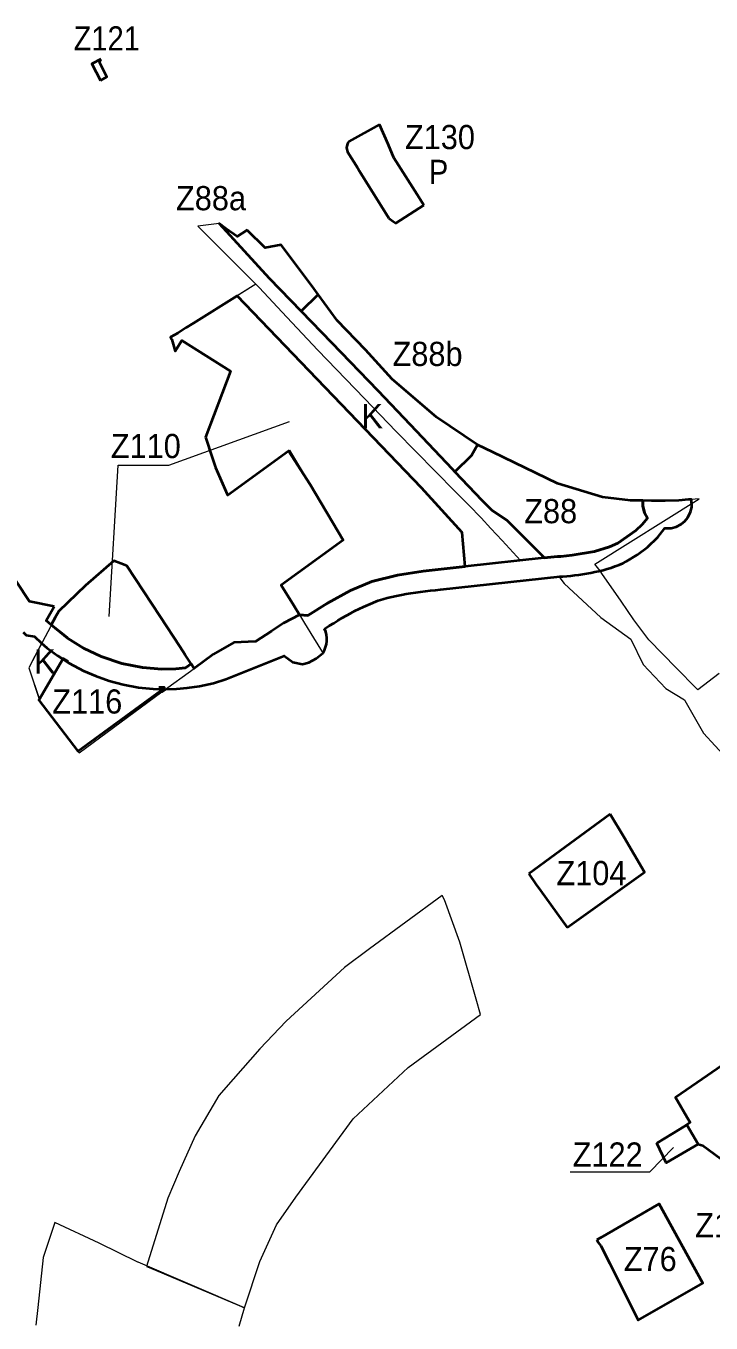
# Model space of a CAD drawing. Extents: x -650276 to -642489, y -1074311 to -1066658.
# Drawn here: x -647405 to -646724, y -1072934 to -1071646 of the extents above; entities that cross this region are included whole.
import ezdxf

# ---------------------------------------------------------------- set-up
doc = ezdxf.new("R2010")
doc.units = 0
doc.header["$LTSCALE"] = 9.6
for name, color, linetype, lineweight in [('44', 7, 'Continuous', 40), ('45', 7, 'Continuous', 40), ('46', 7, 'Continuous', 13), ('47', 7, 'Continuous', 13), ('48', 7, 'Continuous', 13), ('60', 7, 'Continuous', 35), ('63', 7, 'Continuous', 13)]:
    doc.layers.add(name, color=color, linetype=linetype, lineweight=lineweight)

msp = doc.modelspace()

# ---------------------------------------------------------------- linework, layer by layer
at = {"layer": '44'}
msp.add_line((-646978.602, -1072088.66), (-646951.95, -1072116.84), dxfattribs=at)
for points in [[(-646790.432, -1072129.195), (-646791.977, -1072122.305), (-646791.84, -1072117.172), (-646804.27, -1072116.98), (-646832.01, -1072113.66), (-646876.83, -1072100.12), (-646941.054, -1072069.172), (-646956.04, -1072061.95), (-646962.041, -1072072.379), (-646978.602, -1072088.66)], [(-646951.95, -1072116.84), (-646941.45, -1072126.84), (-646927.14, -1072136.74), (-646891.05, -1072172.79), (-646890.044, -1072174.056), (-646876.712, -1072172.592), (-646873.495, -1072172.799), (-646862.09, -1072171.444), (-646840.102, -1072167.623), (-646825.169, -1072163.164), (-646816.74, -1072159.571), (-646799, -1072147), (-646792.58, -1072140.847), (-646787.481, -1072134.643), (-646790.432, -1072129.195)], [(-646808.466, -1072177.78), (-646797.713, -1072171.151), (-646787.223, -1072163.402), (-646777.129, -1072153.576), (-646770.057, -1072144.677), (-646763.959, -1072144.535), (-646758.736, -1072143.137), (-646753.929, -1072140.612), (-646750.164, -1072137.467), (-646747.39, -1072134.069), (-646744.554, -1072128.415), (-646743.411, -1072123.612), (-646743.596, -1072115.985), (-646746.547, -1072116.221), (-646756.298, -1072117), (-646769.668, -1072117.517), (-646783.449, -1072117.302), (-646791.84, -1072117.172)], [(-646791.84, -1072117.172), (-646791.977, -1072122.305), (-646790.432, -1072129.195)], [(-647376.68, -1072222.29), (-647401.221, -1072217.342), (-647451.21, -1072142.08), (-647452.23, -1072134.91)], [(-646790.432, -1072129.195), (-646787.481, -1072134.643), (-646792.58, -1072140.847), (-646799, -1072147), (-646816.74, -1072159.571), (-646825.169, -1072163.164), (-646840.102, -1072167.623), (-646862.09, -1072171.444), (-646873.495, -1072172.799), (-646876.712, -1072172.592), (-646890.044, -1072174.056), (-646968.503, -1072182.672)], [(-646968.503, -1072182.672), (-646995.137, -1072185.597), (-647010.148, -1072187.308), (-647035.515, -1072191.104), (-647060.973, -1072197.439), (-647082.249, -1072206.591), (-647104.989, -1072219.005), (-647124.81, -1072231.168), (-647133, -1072230.754), (-647148.71, -1072238.76)], [(-646851.567, -1072190.155), (-646847.575, -1072189.507), (-646843.569, -1072188.789), (-646843.535, -1072188.782), (-646839.556, -1072187.988), (-646835.538, -1072187.097)], [(-646835.538, -1072187.097), (-646831.517, -1072186.103), (-646827.501, -1072184.997), (-646823.496, -1072183.769), (-646819.509, -1072182.408), (-646815.549, -1072180.906), (-646811.621, -1072179.254), (-646808.466, -1072177.78)], [(-647017.46, -1072208.427), (-647012.612, -1072207.773), (-647007.734, -1072207.162), (-647002.826, -1072206.583), (-646997.894, -1072206.024), (-646992.937, -1072205.475), (-646874.517, -1072192.471), (-646871.271, -1072192.675)], [(-646871.271, -1072192.675), (-646867.371, -1072192.234), (-646867.32, -1072192.228), (-646863.448, -1072191.771), (-646859.506, -1072191.276), (-646855.545, -1072190.741), (-646851.567, -1072190.155)], [(-647108.131, -1072244.373), (-647103.164, -1072241.306), (-647098.944, -1072238.718), (-647094.737, -1072236.177), (-647090.531, -1072233.695), (-647086.322, -1072231.285), (-647082.102, -1072228.962), (-647077.867, -1072226.739), (-647073.611, -1072224.631), (-647069.33, -1072222.651), (-647064.868, -1072220.746), (-647054.841, -1072216.479), (-647050.344, -1072215.107), (-647045.786, -1072213.858), (-647041.174, -1072212.723), (-647036.512, -1072211.693), (-647031.807, -1072210.758), (-647027.061, -1072209.91), (-647022.278, -1072209.136), (-647017.46, -1072208.427)], [(-647240.55, -1072279.42), (-647246.206, -1072283.328), (-647255.671, -1072284.192), (-647269.579, -1072284.489), (-647288.769, -1072283.003), (-647309.416, -1072278.875), (-647330.032, -1072271.935), (-647347.382, -1072263.623), (-647363.317, -1072253.632), (-647363.786, -1072253.254), (-647379.422, -1072240.675), (-647384.567, -1072236.256), (-647376.68, -1072222.29)], [(-647148.71, -1072238.76), (-647160.91, -1072246.82), (-647176.7, -1072257.24), (-647198.3, -1072258.09), (-647218.35, -1072269.67), (-647237.6, -1072283.78), (-647240.55, -1072279.42)], [(-647407.34, -1072247.93), (-647404.45, -1072250.66), (-647396.25, -1072252.14), (-647389.072, -1072258.845)], [(-647389.072, -1072258.845), (-647383.813, -1072263.219), (-647372.858, -1072271.363), (-647361.521, -1072278.584), (-647347.369, -1072286.111)], [(-647205.975, -1072294.599), (-647148.171, -1072271.47), (-647139.697, -1072277.484), (-647130.12, -1072279.44), (-647123.774, -1072277.899)], [(-647123.774, -1072277.899), (-647116.323, -1072273.885), (-647109.812, -1072268.588)], [(-647347.369, -1072286.111), (-647335.382, -1072291.341), (-647321.953, -1072296.073), (-647308.157, -1072299.786), (-647292.715, -1072302.646), (-647278.108, -1072304.147), (-647271.395, -1072304.452), (-647269.52, -1072307.17), (-647265.793, -1072304.439)], [(-647265.793, -1072304.439), (-647255.16, -1072304.123), (-647244.428, -1072303.192), (-647232.368, -1072301.4), (-647218.5, -1072298.335), (-647205.975, -1072294.599)]]:
    msp.add_lwpolyline(points, dxfattribs=at)
msp.add_arc((-647130.12, -1072255.012), 24.428, 326.23773, 25.81772, dxfattribs=at)
at = {"layer": '45'}
for points in [[(-647330.34, -1071678.82), (-647339.211, -1071683.431), (-647330.73, -1071700.09)], [(-647330.73, -1071700.09), (-647324.21, -1071696.2), (-647331.65, -1071681.7), (-647330.34, -1071678.82)], [(-647053.43, -1071743.63), (-647083.97, -1071760.74), (-647084.95, -1071761.98), (-647085.71, -1071763.75), (-647086.19, -1071766.95), (-647085.25, -1071770.69), (-647074.99, -1071786.99), (-647073.19, -1071789.9), (-647044.12, -1071836.68)], [(-647009.514, -1071823.81), (-647016.12, -1071813.35), (-647039.14, -1071776.9), (-647044.83, -1071763.37), (-647053.43, -1071743.63)], [(-647044.12, -1071836.68), (-647040.2, -1071839.6), (-647037.23, -1071841.82), (-647009.514, -1071823.81)], [(-647184.81, -1071848.61), (-647185.62, -1071849.12), (-647194.96, -1071854.93), (-647205.62, -1071847.24), (-647212.66, -1071842.15), (-647163.08, -1071896.13), (-647131.146, -1071929.146)], [(-647131.146, -1071929.146), (-647114.479, -1071912.479), (-647118.79, -1071906.59), (-647151.07, -1071863.08), (-647167.15, -1071866.22), (-647184.81, -1071848.61)], [(-646996.8, -1072034.35), (-647040.89, -1071996.58), (-647067.53, -1071967.54), (-647095.51, -1071938.39), (-647114.479, -1071912.479), (-647131.146, -1071929.146), (-647101.07, -1071960.24)], [(-647101.07, -1071960.24), (-647055.16, -1072007.74), (-647023.04, -1072041.63), (-646981.35, -1072085.77), (-646978.602, -1072088.66), (-646962.041, -1072072.379), (-646956.04, -1072061.95), (-646996.8, -1072034.35)], [(-647362.702, -1072277.035), (-647367.686, -1072273.861), (-647391.761, -1072315.201), (-647353.041, -1072365.971), (-647270.701, -1072305.621), (-647266.974, -1072302.89), (-647272.576, -1072302.903)], [(-646824.42, -1072428.58), (-646878.91, -1072468.54), (-646905.18, -1072487.8)], [(-646824.42, -1072428.58), (-646878.91, -1072468.54), (-646905.18, -1072487.8)], [(-646867.283, -1072540.984), (-646791.569, -1072487.198), (-646790.354, -1072486.136), (-646810.77, -1072451.09), (-646824.42, -1072428.58)], [(-646867.283, -1072540.984), (-646791.569, -1072487.198), (-646790.354, -1072486.136), (-646810.77, -1072451.09), (-646824.42, -1072428.58)], [(-646905.18, -1072487.8), (-646898.1, -1072498.02), (-646893.64, -1072504.45), (-646867.283, -1072540.984)], [(-646905.18, -1072487.8), (-646898.1, -1072498.02), (-646893.64, -1072504.45), (-646867.283, -1072540.984)], [(-646737.05, -1072756.4), (-646732.5, -1072757.63), (-646708.65, -1072775.02), (-646702.45, -1072773.39), (-646712.46, -1072766.76), (-646711.79, -1072750.02), (-646677.39, -1072724.85), (-646660.89, -1072709.97), (-646643.36, -1072746.04), (-646647.93, -1072759.01), (-646612.11, -1072774.56), (-646581.92, -1072723.91), (-646589.37, -1072709.83), (-646605.23, -1072679.37), (-646627.32, -1072636.95), (-646629.86, -1072632.07), (-646648.27, -1072647.48), (-646669.6, -1072654.53), (-646697.89, -1072667.65)], [(-646697.89, -1072667.65), (-646732.95, -1072691.68), (-646759.491, -1072709.878), (-646757.5, -1072713.3), (-646747.87, -1072729.85), (-646744.94, -1072734.88), (-646748.3, -1072737.01), (-646737.05, -1072756.4)]]:
    msp.add_lwpolyline(points, dxfattribs=at)
for points in [[(-647226.41, -1072054.11), (-647219.64, -1072074.29), (-647216.23, -1072084.14), (-647204.78, -1072110.92), (-647204.38, -1072111.87), (-647143.76, -1072067.69), (-647122.33, -1072101.34), (-647089.54, -1072156.53), (-647134.17, -1072188.95), (-647151.05, -1072201.21), (-647138.65, -1072221.5), (-647133, -1072230.754), (-647124.81, -1072231.168), (-647104.989, -1072219.005), (-647082.249, -1072206.591), (-647060.973, -1072197.439), (-647035.515, -1072191.104), (-647010.148, -1072187.308), (-646995.137, -1072185.597), (-646968.503, -1072182.672), (-646971.283, -1072148.82), (-647011.762, -1072104.502), (-647194.903, -1071913.941), (-647238.1, -1071941), (-647245.71, -1071945.77), (-647253.67, -1071950.76), (-647261.12, -1071954.82), (-647259.7, -1071957.06), (-647256.53, -1071968.64), (-647253.85, -1071964.38), (-647249.92, -1071958.12), (-647201.53, -1071988.71)], [(-647226.41, -1072054.11), (-647219.64, -1072074.29), (-647216.23, -1072084.14), (-647204.78, -1072110.92), (-647204.38, -1072111.87), (-647143.76, -1072067.69), (-647122.33, -1072101.34), (-647089.54, -1072156.53), (-647134.17, -1072188.95), (-647151.05, -1072201.21), (-647138.65, -1072221.5), (-647133, -1072230.754), (-647124.81, -1072231.168), (-647104.989, -1072219.005), (-647082.249, -1072206.591), (-647060.973, -1072197.439), (-647035.515, -1072191.104), (-647010.148, -1072187.308), (-646995.137, -1072185.597), (-646968.503, -1072182.672), (-646971.283, -1072148.82), (-647011.762, -1072104.502), (-647194.903, -1071913.941), (-647238.1, -1071941), (-647245.71, -1071945.77), (-647253.67, -1071950.76), (-647261.12, -1071954.82), (-647259.7, -1071957.06), (-647256.53, -1071968.64), (-647253.85, -1071964.38), (-647249.92, -1071958.12), (-647201.53, -1071988.71)], [(-647246.563, -1072270.214), (-647251.85, -1072262.12), (-647271.38, -1072232.23), (-647304.32, -1072181.81), (-647310.33, -1072179.58), (-647317.33, -1072176.99), (-647345.42, -1072201.58), (-647372.1, -1072226.89), (-647375.551, -1072233.387), (-647379.422, -1072240.675), (-647363.317, -1072253.632), (-647347.382, -1072263.623), (-647330.032, -1072271.935), (-647309.416, -1072278.875), (-647288.769, -1072283.003), (-647269.579, -1072284.489), (-647255.671, -1072284.192), (-647246.206, -1072283.328), (-647240.55, -1072279.42)], [(-647246.563, -1072270.214), (-647251.85, -1072262.12), (-647271.38, -1072232.23), (-647304.32, -1072181.81), (-647310.33, -1072179.58), (-647317.33, -1072176.99), (-647345.42, -1072201.58), (-647372.1, -1072226.89), (-647375.551, -1072233.387), (-647379.422, -1072240.675), (-647363.317, -1072253.632), (-647347.382, -1072263.623), (-647330.032, -1072271.935), (-647309.416, -1072278.875), (-647288.769, -1072283.003), (-647269.579, -1072284.489), (-647255.671, -1072284.192), (-647246.206, -1072283.328), (-647240.55, -1072279.42)], [(-646778.2, -1072755.19), (-646755.1, -1072741.28), (-646748.3, -1072737.01), (-646737.05, -1072756.4), (-646768.74, -1072774.78)], [(-646837.81, -1072851.3), (-646836.5, -1072853.76), (-646833.67, -1072857.15), (-646824.89, -1072874.66), (-646796.68, -1072930.92), (-646732.28, -1072894.29), (-646775.85, -1072815.39), (-646834.08, -1072849.15)], [(-646837.81, -1072851.3), (-646836.5, -1072853.76), (-646833.67, -1072857.15), (-646824.89, -1072874.66), (-646796.68, -1072930.92), (-646732.28, -1072894.29), (-646775.85, -1072815.39), (-646834.08, -1072849.15)]]:
    msp.add_lwpolyline(points, close=True, dxfattribs=at)
msp.add_arc((-646767.624, -1072120.384), 24.428, 264.28146, 264.89913, dxfattribs=at)
msp.add_arc((-646767.624, -1072120.384), 24.428, 264.28146, 264.89913, dxfattribs=at)
at = {"layer": '46'}
for points in [[(-647321.863, -1072232.262), (-647313.149, -1072082.081), (-647262.801, -1072082.081), (-647142.741, -1072038.48)], [(-647321.863, -1072232.262), (-647313.149, -1072082.081), (-647262.801, -1072082.081), (-647142.741, -1072038.48)], [(-646864.278, -1072783.783), (-646784.878, -1072783.783), (-646761.687, -1072759.411)]]:
    msp.add_lwpolyline(points, dxfattribs=at)
at = {"layer": '47'}
msp.add_line((-647391.346, -1072314.489), (-647368.024, -1072274.442), dxfattribs=at)
for points in [[(-646913.373, -1072176.618), (-646931.653, -1072156.802), (-646942.78, -1072144.74), (-646952.48, -1072134.22), (-646964.8, -1072121.83), (-646977.59, -1072108.96), (-646978.45, -1072108.09), (-647036.8, -1072048.41), (-647068.31, -1072015.68), (-647114.59, -1071967.77), (-647145.38, -1071935), (-647173.14, -1071905.45), (-647174.57, -1071904.06), (-647176.32, -1071902.3), (-647194.902, -1071913.942), (-647011.762, -1072104.502)], [(-647011.762, -1072104.502), (-646971.283, -1072148.82), (-646968.503, -1072182.672), (-646913.373, -1072176.618)], [(-646716.167, -1072288.809), (-646737.449, -1072305.019), (-646738.951, -1072303.49), (-646758.684, -1072283.41), (-646785.958, -1072255.505), (-646800.76, -1072235.668), (-646813.508, -1072217.089), (-646813.516, -1072217.078), (-646832.718, -1072189.697), (-646834.279, -1072186.818), (-646835.199, -1072187.013), (-646835.538, -1072187.097), (-646839.556, -1072187.988), (-646843.535, -1072188.782), (-646843.569, -1072188.789), (-646847.575, -1072189.507), (-646851.567, -1072190.155), (-646855.545, -1072190.741), (-646859.506, -1072191.276), (-646863.448, -1072191.771), (-646867.32, -1072192.228), (-646867.371, -1072192.234), (-646871.271, -1072192.675), (-646873.131, -1072192.558), (-646875.509, -1072192.58), (-646870.21, -1072199.51), (-646833.75, -1072233.32), (-646803.98, -1072254.74), (-646791.59, -1072279.78), (-646769.24, -1072303.65), (-646750.58, -1072315.02), (-646750.12, -1072315.82), (-646742.32, -1072329.62), (-646731.82, -1072348.2), (-646696.83, -1072385.81)], [(-647389.072, -1072258.845), (-647391.3, -1072263.04), (-647401.88, -1072283.4), (-647391.346, -1072314.489)], [(-647368.024, -1072274.442), (-647372.858, -1072271.363), (-647372.858, -1072271.363), (-647383.813, -1072263.219), (-647389.072, -1072258.845)], [(-647192.93, -1072936.82), (-647187.445, -1072918.804), (-647293.317, -1072873.549), (-647293.351, -1072873.533), (-647331.82, -1072854.49), (-647375.92, -1072833.99), (-647387.64, -1072868.69), (-647392.96, -1072918.277), (-647394.87, -1072936.08)]]:
    msp.add_lwpolyline(points, dxfattribs=at)
msp.add_lwpolyline([(-647284.75, -1072877.79), (-647282.31, -1072878.82), (-647192.718, -1072916.582), (-647187.445, -1072918.804), (-647172.48, -1072872.92), (-647155.72, -1072836.46), (-647136.69, -1072808.98), (-647079.74, -1072731.1), (-647025.04, -1072679.96), (-646953.2, -1072627.45), (-646957.5, -1072612.09), (-646973.68, -1072555.68), (-646989.01, -1072513.62), (-646991.24, -1072509.24), (-647063.38, -1072562.42), (-647088.397, -1072580.865), (-647088.4, -1072580.868), (-647146.21, -1072634.02), (-647172.36, -1072661.69), (-647198.77, -1072691.71), (-647212.92, -1072708.05), (-647236.54, -1072748.09), (-647252.29, -1072783.24), (-647263.58, -1072809.97)], close=True, dxfattribs=at)
at = {"layer": '63'}
for points in [[(-646834.279, -1072186.818), (-646839.631, -1072180.339), (-646736.02, -1072115.38), (-646763.93, -1072117.61), (-646771.31, -1072117.49), (-646806.87, -1072116.94), (-646832.01, -1072113.66), (-646868.61, -1072102.6), (-646876.83, -1072100.12), (-646956.04, -1072061.95), (-646996.8, -1072034.35), (-647040.89, -1071996.58), (-647067.53, -1071967.54), (-647095.51, -1071938.39), (-647151.07, -1071863.08), (-647167.15, -1071866.22), (-647184.81, -1071848.61), (-647194.96, -1071854.93), (-647212.66, -1071842.15), (-647233.81, -1071844.66), (-647209.94, -1071868.59), (-647194.128, -1071884.447), (-647176.32, -1071902.3), (-647253.67, -1071950.76), (-647261.12, -1071954.82), (-647259.7, -1071957.06), (-647256.53, -1071968.64), (-647253.85, -1071964.38), (-647249.92, -1071958.12), (-647201.53, -1071988.71), (-647226.41, -1072054.11), (-647219.64, -1072074.29), (-647216.23, -1072084.14), (-647204.38, -1072111.87), (-647143.76, -1072067.69), (-647142.77, -1072067), (-647122.33, -1072101.34), (-647105.82, -1072129.3), (-647089.54, -1072156.53), (-647134.17, -1072188.95), (-647151.05, -1072201.21), (-647138.65, -1072221.5), (-647128.07, -1072238.83), (-647119.07, -1072253.56), (-647110.55, -1072267.42), (-647109.812, -1072268.588)], [(-647351.86, -1072367.52), (-647269.52, -1072307.17), (-647237.6, -1072283.78), (-647240.55, -1072279.42), (-647251.85, -1072262.12), (-647271.38, -1072232.23), (-647304.32, -1072181.81), (-647310.33, -1072179.58), (-647317.33, -1072176.99), (-647345.589, -1072201.74), (-647372.1, -1072226.89), (-647391.3, -1072263.04), (-647395.732, -1072271.563), (-647401.88, -1072283.4)], [(-647036.512, -1072211.693), (-647007.734, -1072207.162), (-646931.123, -1072198.687), (-646875.509, -1072192.58), (-646873.131, -1072192.558), (-646871.271, -1072192.675), (-646867.371, -1072192.234), (-646855.545, -1072190.741), (-646843.569, -1072188.789), (-646834.279, -1072186.818)], [(-647109.812, -1072268.588), (-647107.628, -1072264.478), (-647105.844, -1072257.729), (-647105.736, -1072254.456), (-647106.013, -1072251.237), (-647106.779, -1072247.831), (-647108.131, -1072244.373), (-647080.548, -1072228.146), (-647054.841, -1072216.479), (-647036.512, -1072211.693), (-647036.512, -1072211.693)], [(-647401.88, -1072283.4), (-647390.58, -1072316.75), (-647351.86, -1072367.52)], [(-646810.77, -1072451.09), (-646810.77, -1072451.09), (-646824.42, -1072428.58), (-646850.71, -1072447.86), (-646878.91, -1072468.54), (-646905.18, -1072487.8), (-646898.1, -1072498.02), (-646893.64, -1072504.45), (-646867.283, -1072540.984)], [(-646867.283, -1072540.984), (-646790.354, -1072486.136), (-646810.77, -1072451.09)], [(-646796.68, -1072930.92), (-646732.28, -1072894.29), (-646775.85, -1072815.39), (-646837.81, -1072851.3)], [(-646837.81, -1072851.3), (-646836.5, -1072853.76), (-646833.67, -1072857.15), (-646824.89, -1072874.66), (-646796.68, -1072930.92)]]:
    msp.add_lwpolyline(points, dxfattribs=at)

# ---------------------------------------------------------------- texts
at = {"layer": '44', "width": 0.95}
msp.add_text('Z88', height=24, dxfattribs=at).set_placement((-646909.741, -1072139.634))
msp.add_text('Z88', height=24, dxfattribs=at).set_placement((-646909.741, -1072139.634))
at = {"layer": '46'}
for s, width, p in [('Z121', 0.9, (-647357.291, -1071670.187)), ('Z130', 0.95, (-647028.202, -1071768.178)), ('Z88a', 0.95, (-647255.564, -1071828.861)), ('Z88b', 0.95, (-647040.507, -1071983.505)), ('Z110', 0.95, (-647320.328, -1072074.974)), ('Z110', 0.95, (-647320.328, -1072074.974)), ('Z116', 0.95, (-647378.432, -1072328.636)), ('Z104', 0.95, (-646877.745, -1072499.058)), ('Z104', 0.95, (-646877.745, -1072499.058)), ('Z122', 0.95, (-646861.605, -1072778.534)), ('Z126', 0.95, (-646740.041, -1072848.718)), ('Z76', 0.95, (-646810.899, -1072882.315)), ('Z76', 0.95, (-646810.899, -1072882.315))]:
    msp.add_text(s, height=24, dxfattribs=dict(at, width=width)).set_placement(p)
at = {"layer": '48'}
for p in [(-647071.498, -1072045.307), (-647396.507, -1072288.9)]:
    msp.add_text('K', height=24, dxfattribs=at).set_placement(p)
at = {"layer": '60', "width": 0.9}
msp.add_text('P', height=24, dxfattribs=at).set_placement((-647004.438, -1071802.773))

doc.saveas('drawing.dxf')
